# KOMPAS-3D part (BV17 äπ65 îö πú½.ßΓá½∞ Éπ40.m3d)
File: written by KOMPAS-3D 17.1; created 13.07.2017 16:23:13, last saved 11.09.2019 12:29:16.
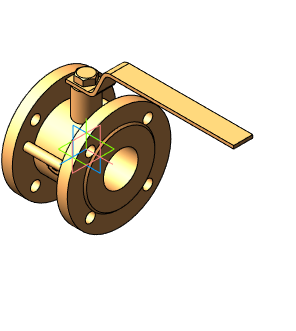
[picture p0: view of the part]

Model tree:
1. Операция без истории:3  (labels: Сталь 20  ГОСТ 1050-88)

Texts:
  DISO1
  DISO2
  BV17 Ду10 ФФ Ру40 угл. сталь
  BV17 Ду15 ФФ Ру40 угл. сталь
  BV17 Ду20 ФФ Ру40 угл. сталь
  BV17 Ду25 ФФ Ру40 угл. сталь
  BV17 Ду32 ФФ Ру40 угл. сталь
  BV17 Ду40 ФФ Ру40 угл. сталь
  BV17 Ду50 ФФ Ру40 угл. сталь
  BV17 Ду65 ФФ Ру40 угл. сталь
  BV17 Ду80 ФФ Ру40 угл. сталь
